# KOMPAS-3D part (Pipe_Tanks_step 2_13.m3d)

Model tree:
1. X Axis
2. Y Axis
3. Z Axis  (labels: Pipe Dn 50)
     Òîëùèíà ñòåíêè 1 = 1

Referenced files in C:\Documents and Settings\kashirsky\Мои документы\Camtasia Studio\Pipelines3D\Tanks\: Tanks_step 2.a3d
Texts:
  Pipe Dn 50
  Steel ASTM A295
  Three Point Plane
  Plane at Angle
  Line and Point Plane
  Axis through Two Vertices
  Axis of Feature
  Axis of Conical Surface
  Axis through Edge
  Trim by Surface
  Trim by Sketch
  Feature with No History
  Intersection Axis of Two Planes
  Two Line Plane
  Line and Face Plane
  Bend by line
  Hole in sheet body
  Cut in sheet body
  Point in CM
  Linear Dimension from Line to Point
  Surface Finish Symbol
  Geometric Tolerance Symbol
  Leader #1
  Leader #2
  Leader #3
  Shape Deviations and Datum
  Node point number
  Mark of coordination axis
  Node point designation
  Mark/Reference designation with leader
  Mark/reference designation on line
  Mark/Reference designation without leader
  Plane of section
